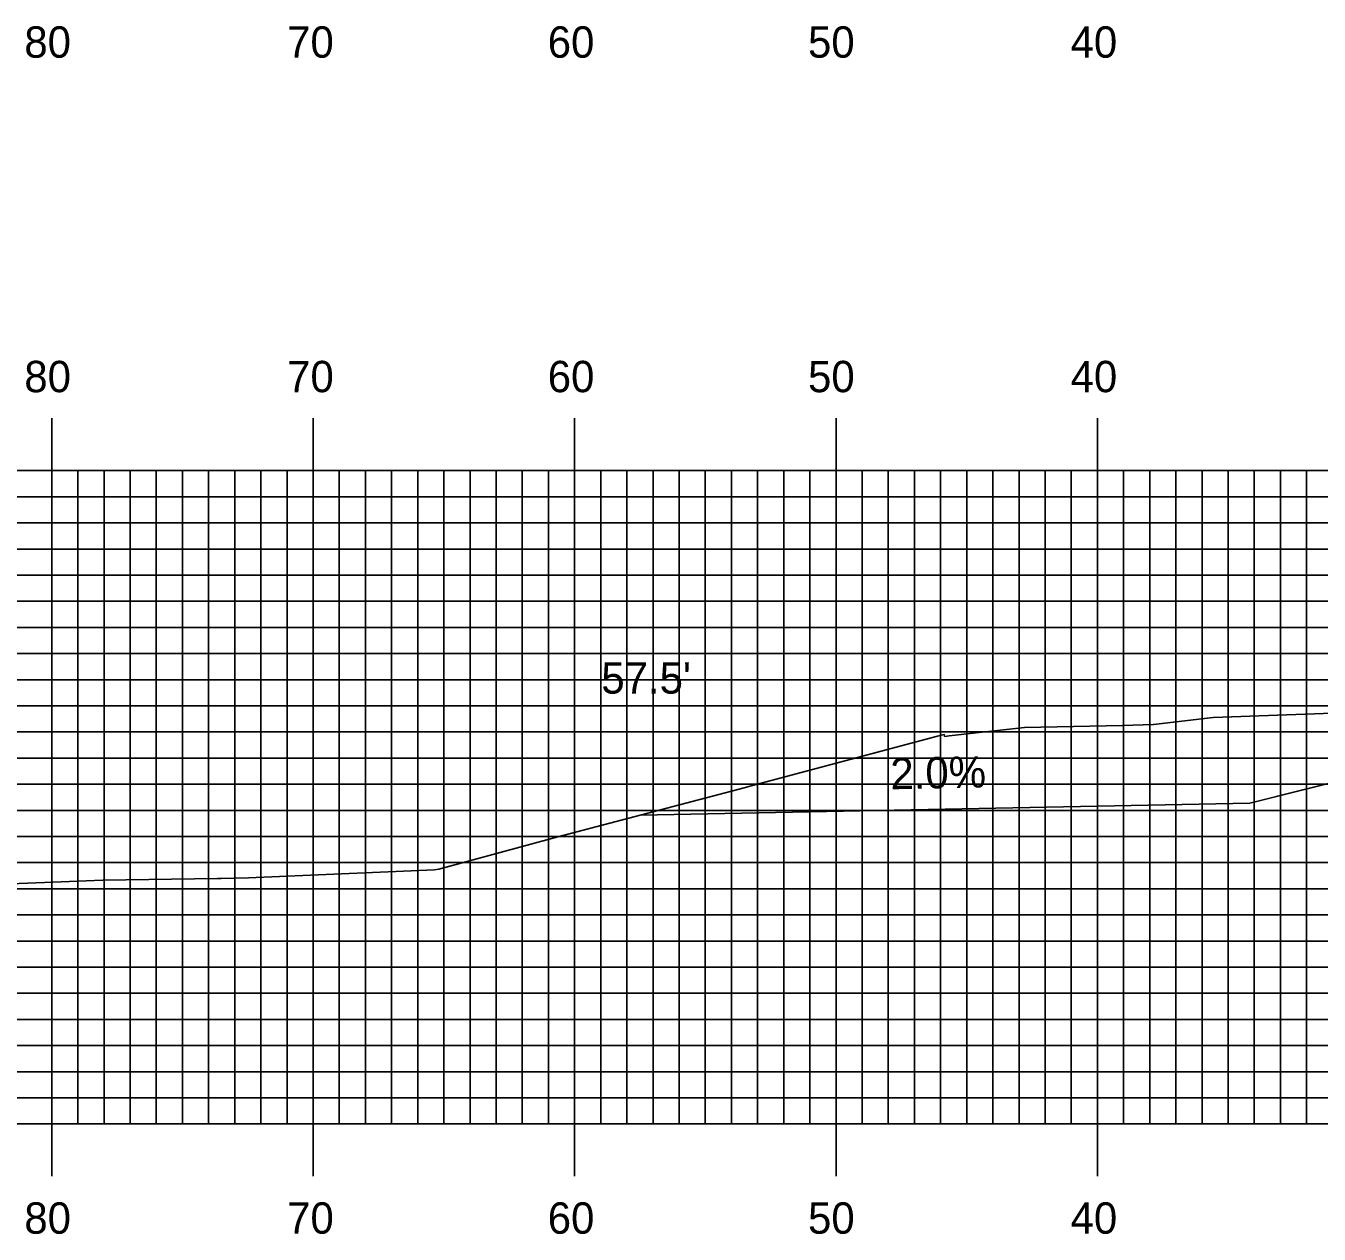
# Model space of a CAD drawing. Extents: x 1823571 to 1823914, y 442310 to 442530.
# Drawn here: x 1823655.91 to 1823705.38, y 442368.9 to 442415.13 of the extents above; entities that cross this region are included whole.
import ezdxf

# ---------------------------------------------------------------- set-up
doc = ezdxf.new("R2010")
doc.units = 0
for name, color, linetype in [('ANNOTATION', 7, 'Continuous'), ('D_Roadway_Centerline', 7, 'Continuous'), ('D_Roadway_SlopeLines', 7, 'Continuous'), ('D_Text_Standard', 7, 'Continuous'), ('H_V ANNOTATION', 7, 'Continuous'), ('MAJOR', 7, 'Continuous'), ('MINOR', 7, 'Continuous'), ('S_Roadway_Centerline', 7, 'Continuous')]:
    doc.layers.add(name, color=color, linetype=linetype)

msp = doc.modelspace()

# ---------------------------------------------------------------- linework, layer by layer
at = {"layer": 'D_Roadway_Centerline'}
msp.add_lwpolyline([(1823679.402, 442384.927), (1823702.726, 442385.394), (1823706.726, 442386.394), (1823716.9, 442388.937), (1823724.9, 442389.257), (1823736.9, 442389.497), (1823748.9, 442389.257), (1823756.9, 442388.937), (1823767.074, 442386.394), (1823771.074, 442385.394), (1823776.57, 442384.02)], dxfattribs=at)
at = {"layer": 'D_Roadway_SlopeLines'}
msp.add_lwpolyline([(1823716.9, 442388.937), (1823702.726, 442385.394), (1823679.402, 442384.927)], dxfattribs=at)
at = {"layer": 'MAJOR'}
for p, q in [((1823656.9, 442400.119), (1823656.9, 442398.115)), ((1823666.9, 442400.119), (1823666.9, 442398.115)), ((1823676.9, 442400.119), (1823676.9, 442398.115)), ((1823686.9, 442400.119), (1823686.9, 442398.115)), ((1823696.9, 442400.119), (1823696.9, 442398.115)), ((1823596.9, 442398.115), (1823876.9, 442398.115)), ((1823596.9, 442398.115), (1823876.9, 442398.115)), ((1823656.9, 442373.115), (1823656.9, 442398.115)), ((1823666.9, 442373.115), (1823666.9, 442398.115)), ((1823676.9, 442373.115), (1823676.9, 442398.115)), ((1823686.9, 442373.115), (1823686.9, 442398.115)), ((1823696.9, 442373.115), (1823696.9, 442398.115)), ((1823596.9, 442393.115), (1823876.9, 442393.115)), ((1823596.9, 442388.115), (1823876.9, 442388.115)), ((1823596.9, 442383.115), (1823876.9, 442383.115)), ((1823596.9, 442378.115), (1823876.9, 442378.115)), ((1823596.9, 442373.115), (1823876.9, 442373.115)), ((1823656.9, 442371.111), (1823656.9, 442373.115)), ((1823666.9, 442371.111), (1823666.9, 442373.115)), ((1823676.9, 442371.111), (1823676.9, 442373.115)), ((1823686.9, 442371.111), (1823686.9, 442373.115)), ((1823696.9, 442371.111), (1823696.9, 442373.115))]:
    msp.add_line(p, q, dxfattribs=at)
at = {"layer": 'MINOR'}
for p, q in [((1823657.9, 442373.115), (1823657.9, 442398.115)), ((1823658.9, 442373.115), (1823658.9, 442398.115)), ((1823659.9, 442373.115), (1823659.9, 442398.115)), ((1823660.9, 442373.115), (1823660.9, 442398.115)), ((1823661.9, 442373.115), (1823661.9, 442398.115)), ((1823662.9, 442373.115), (1823662.9, 442398.115)), ((1823663.9, 442373.115), (1823663.9, 442398.115)), ((1823664.9, 442373.115), (1823664.9, 442398.115)), ((1823665.9, 442373.115), (1823665.9, 442398.115)), ((1823667.9, 442373.115), (1823667.9, 442398.115)), ((1823668.9, 442373.115), (1823668.9, 442398.115)), ((1823669.9, 442373.115), (1823669.9, 442398.115)), ((1823670.9, 442373.115), (1823670.9, 442398.115)), ((1823671.9, 442373.115), (1823671.9, 442398.115)), ((1823672.9, 442373.115), (1823672.9, 442398.115)), ((1823673.9, 442373.115), (1823673.9, 442398.115)), ((1823674.9, 442373.115), (1823674.9, 442398.115)), ((1823675.9, 442373.115), (1823675.9, 442398.115)), ((1823677.9, 442373.115), (1823677.9, 442398.115)), ((1823678.9, 442373.115), (1823678.9, 442398.115)), ((1823679.9, 442373.115), (1823679.9, 442398.115)), ((1823680.9, 442373.115), (1823680.9, 442398.115)), ((1823681.9, 442373.115), (1823681.9, 442398.115)), ((1823682.9, 442373.115), (1823682.9, 442398.115)), ((1823683.9, 442373.115), (1823683.9, 442398.115)), ((1823684.9, 442373.115), (1823684.9, 442398.115)), ((1823685.9, 442373.115), (1823685.9, 442398.115)), ((1823687.9, 442373.115), (1823687.9, 442398.115)), ((1823688.9, 442373.115), (1823688.9, 442398.115)), ((1823689.9, 442373.115), (1823689.9, 442398.115)), ((1823690.9, 442373.115), (1823690.9, 442398.115)), ((1823691.9, 442373.115), (1823691.9, 442398.115)), ((1823692.9, 442373.115), (1823692.9, 442398.115)), ((1823693.9, 442373.115), (1823693.9, 442398.115)), ((1823694.9, 442373.115), (1823694.9, 442398.115)), ((1823695.9, 442373.115), (1823695.9, 442398.115)), ((1823697.9, 442373.115), (1823697.9, 442398.115)), ((1823698.9, 442373.115), (1823698.9, 442398.115)), ((1823699.9, 442373.115), (1823699.9, 442398.115)), ((1823700.9, 442373.115), (1823700.9, 442398.115)), ((1823701.9, 442373.115), (1823701.9, 442398.115)), ((1823702.9, 442373.115), (1823702.9, 442398.115)), ((1823703.9, 442373.115), (1823703.9, 442398.115)), ((1823704.9, 442373.115), (1823704.9, 442398.115)), ((1823596.9, 442397.115), (1823876.9, 442397.115)), ((1823596.9, 442396.115), (1823876.9, 442396.115)), ((1823596.9, 442395.115), (1823876.9, 442395.115)), ((1823596.9, 442394.115), (1823876.9, 442394.115)), ((1823596.9, 442392.115), (1823876.9, 442392.115)), ((1823596.9, 442391.115), (1823876.9, 442391.115)), ((1823596.9, 442390.115), (1823876.9, 442390.115)), ((1823596.9, 442389.115), (1823876.9, 442389.115)), ((1823596.9, 442387.115), (1823876.9, 442387.115)), ((1823596.9, 442386.115), (1823876.9, 442386.115)), ((1823596.9, 442385.115), (1823876.9, 442385.115)), ((1823596.9, 442384.115), (1823876.9, 442384.115)), ((1823596.9, 442382.115), (1823876.9, 442382.115)), ((1823596.9, 442381.115), (1823876.9, 442381.115)), ((1823596.9, 442380.115), (1823876.9, 442380.115)), ((1823596.9, 442379.115), (1823876.9, 442379.115)), ((1823596.9, 442377.115), (1823876.9, 442377.115)), ((1823596.9, 442376.115), (1823876.9, 442376.115)), ((1823596.9, 442375.115), (1823876.9, 442375.115)), ((1823596.9, 442374.115), (1823876.9, 442374.115))]:
    msp.add_line(p, q, dxfattribs=at)
at = {"layer": 'S_Roadway_Centerline'}
msp.add_lwpolyline([(1823639.986, 442381.697), (1823658.855, 442382.444), (1823663.243, 442382.503), (1823663.382, 442382.504), (1823664.431, 442382.529), (1823671.544, 442382.838), (1823671.705, 442382.859), (1823676.264, 442384.103), (1823683.381, 442385.972), (1823683.652, 442386.054), (1823690.779, 442387.956), (1823691.039, 442388.014), (1823691.053, 442387.946), (1823691.23, 442387.965), (1823694.11, 442388.279), (1823697.854, 442388.358), (1823699.039, 442388.4), (1823701.322, 442388.663), (1823711.186, 442389.029)], dxfattribs=at)

# ---------------------------------------------------------------- texts
at = {"layer": 'ANNOTATION'}
msp.add_text('2.0%', height=1.2, rotation=1.1458, dxfattribs=at).set_placement((1823688.991, 442385.919))
at = {"layer": 'D_Text_Standard'}
msp.add_text("57.5'", height=1.2, dxfattribs=at).set_placement((1823677.922, 442389.581))
at = {"layer": 'H_V ANNOTATION'}
for s, p in [('80', (1823655.851, 442413.915)), ('70', (1823665.904, 442413.915)), ('60', (1823675.872, 442413.915)), ('50', (1823685.829, 442413.915)), ('40', (1823695.872, 442413.915)), ('80', (1823655.851, 442401.115)), ('70', (1823665.904, 442401.115)), ('60', (1823675.872, 442401.115)), ('50', (1823685.829, 442401.115)), ('40', (1823695.872, 442401.115)), ('80', (1823655.851, 442368.915)), ('70', (1823665.904, 442368.915)), ('60', (1823675.872, 442368.915)), ('50', (1823685.829, 442368.915)), ('40', (1823695.872, 442368.915))]:
    msp.add_text(s, height=1.2, dxfattribs=at).set_placement(p)

doc.saveas('drawing.dxf')
